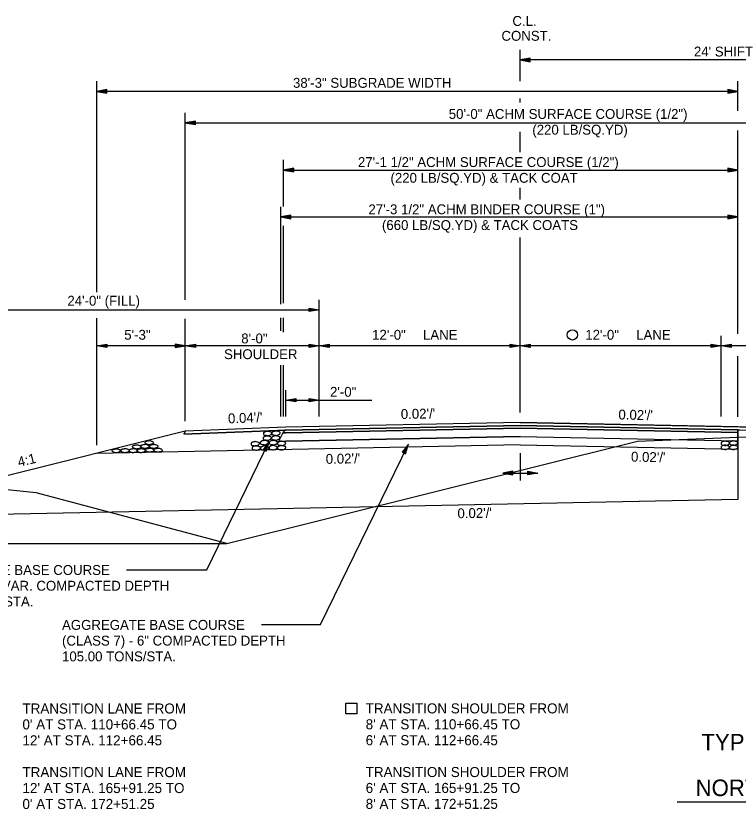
# Model space of a CAD drawing. Extents: x 1398565 to 1398920, y 1968324 to 1968581.
# Drawn here: x 1398599.68 to 1398642.81, y 1968480.86 to 1968528.22 of the extents above; entities that cross this region are included whole.
import ezdxf

# ---------------------------------------------------------------- set-up
doc = ezdxf.new("R2010")
doc.units = 0
for name, color, linetype in [('1', 7, 'Continuous'), ('10', 7, 'Continuous'), ('19', 7, 'Continuous'), ('42', 7, 'Continuous'), ('7', 7, 'Continuous'), ('Level 1', 7, 'Continuous')]:
    doc.layers.add(name, color=color, linetype=linetype)

# ---------------------------------------------------------------- blocks, each defined once
blk = doc.blocks.new('ROCKS')
at = {"layer": '1'}
blk.add_spline([(0.013, 0.06), (0.053, 0.053), (0.107, 0.033), (0.133, 0.013), (0.133, -0.007), (0.12, -0.033), (0.107, -0.04), (0.073, -0.053), (0.033, -0.067), (0.013, -0.067), (-0.02, -0.06), (-0.06, -0.053), (-0.087, -0.047), (-0.113, -0.02), (-0.113, -0.007), (-0.107, 0.02), (-0.087, 0.033), (-0.067, 0.047), (-0.033, 0.053), (-0.02, 0.06), (0.013, 0.06)], degree=3, dxfattribs=at)
blk = doc.blocks.new('4TO1 ABC')
at = {"layer": '1', "xscale": 0.1312491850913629, "yscale": 0.1312491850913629, "rotation": 180}
for p in [(0.00175, -0.00875), (-0.03325, -0.0385), (-0.016625, -0.023625), (0, -0.0385), (0.018375, -0.023625), (0.034125, -0.04025), (0.051625, -0.025375), (0.06475, -0.04025), (0.098, -0.04025), (0.133, -0.041125)]:
    blk.add_blockref('ROCKS', p, dxfattribs=at)

msp = doc.modelspace()

# ---------------------------------------------------------------- linework, layer by layer
at = {"layer": '10'}
msp.add_lwpolyline([(1398619.391, 1968487.191), (1398620.032, 1968487.191), (1398620.032, 1968486.549), (1398619.391, 1968486.549)], close=True, dxfattribs=at)
msp.add_circle((1398632.909, 1968509.169), 0.306, dxfattribs=at)
at = {"layer": '19'}
for p, q in [((1398630.395, 1968525.69), (1398629.795, 1968525.585)), ((1398653.795, 1968525.585), (1398629.795, 1968525.585)), ((1398629.795, 1968525.585), (1398630.395, 1968525.48)), ((1398630.395, 1968525.635), (1398629.955, 1968525.6)), ((1398629.955, 1968525.57), (1398630.395, 1968525.53)), ((1398630.395, 1968525.48), (1398630.395, 1968525.69)), ((1398604.509, 1968511.718), (1398604.509, 1968524.31)), ((1398642.795, 1968522.541), (1398642.795, 1968524.31)), ((1398605.109, 1968523.815), (1398604.509, 1968523.71)), ((1398642.795, 1968523.71), (1398604.509, 1968523.71)), ((1398604.509, 1968523.71), (1398605.109, 1968523.605)), ((1398605.109, 1968523.76), (1398604.669, 1968523.725)), ((1398604.669, 1968523.695), (1398605.109, 1968523.655)), ((1398605.109, 1968523.605), (1398605.109, 1968523.815)), ((1398642.195, 1968523.815), (1398642.195, 1968523.605)), ((1398642.795, 1968523.71), (1398642.195, 1968523.815)), ((1398642.635, 1968523.725), (1398642.195, 1968523.76)), ((1398642.195, 1968523.605), (1398642.795, 1968523.71)), ((1398642.195, 1968523.655), (1398642.635, 1968523.695)), ((1398609.795, 1968511.264), (1398609.795, 1968522.435)), ((1398610.395, 1968521.94), (1398609.795, 1968521.835)), ((1398609.795, 1968521.835), (1398659.795, 1968521.835)), ((1398609.795, 1968521.835), (1398610.395, 1968521.73)), ((1398610.395, 1968521.885), (1398609.955, 1968521.85)), ((1398609.955, 1968521.82), (1398610.395, 1968521.78)), ((1398610.395, 1968521.73), (1398610.395, 1968521.94)), ((1398642.795, 1968509.227), (1398642.795, 1968521.383)), ((1398615.667, 1968516.846), (1398615.667, 1968519.613)), ((1398616.267, 1968519.118), (1398615.667, 1968519.013)), ((1398615.667, 1968519.013), (1398616.267, 1968518.908)), ((1398615.667, 1968519.013), (1398642.795, 1968519.013)), ((1398616.267, 1968519.063), (1398615.827, 1968519.028)), ((1398615.827, 1968518.998), (1398616.267, 1968518.958)), ((1398616.267, 1968518.908), (1398616.267, 1968519.118)), ((1398642.195, 1968519.118), (1398642.195, 1968518.908)), ((1398642.795, 1968519.013), (1398642.195, 1968519.118)), ((1398642.635, 1968519.028), (1398642.195, 1968519.063)), ((1398642.195, 1968518.908), (1398642.795, 1968519.013)), ((1398642.195, 1968518.958), (1398642.635, 1968518.998)), ((1398615.497, 1968511.016), (1398615.497, 1968516.815)), ((1398616.097, 1968516.32), (1398615.497, 1968516.215)), ((1398615.497, 1968516.215), (1398642.795, 1968516.215)), ((1398615.497, 1968516.215), (1398616.097, 1968516.11)), ((1398616.097, 1968516.265), (1398615.657, 1968516.23)), ((1398615.657, 1968516.2), (1398616.097, 1968516.16)), ((1398616.097, 1968516.11), (1398616.097, 1968516.32)), ((1398642.195, 1968516.32), (1398642.195, 1968516.11)), ((1398642.795, 1968516.215), (1398642.195, 1968516.32)), ((1398642.635, 1968516.23), (1398642.195, 1968516.265)), ((1398642.195, 1968516.11), (1398642.795, 1968516.215)), ((1398642.195, 1968516.16), (1398642.635, 1968516.2)), ((1398615.667, 1968511.057), (1398615.667, 1968515.688)), ((1398617.795, 1968504.296), (1398617.795, 1968511.264)), ((1398593.795, 1968510.664), (1398617.795, 1968510.664)), ((1398617.195, 1968510.559), (1398617.195, 1968510.769)), ((1398617.195, 1968510.769), (1398617.795, 1968510.664)), ((1398617.195, 1968510.714), (1398617.635, 1968510.679)), ((1398617.795, 1968510.664), (1398617.195, 1968510.559)), ((1398617.635, 1968510.649), (1398617.195, 1968510.609)), ((1398604.509, 1968502.584), (1398604.509, 1968510.168)), ((1398609.795, 1968504.017), (1398609.795, 1968510.127)), ((1398615.497, 1968509.424), (1398615.497, 1968510.189)), ((1398615.667, 1968509.341), (1398615.667, 1968510.189)), ((1398641.795, 1968504.296), (1398641.795, 1968509.12)), ((1398604.509, 1968508.52), (1398605.109, 1968508.625)), ((1398631.795, 1968508.52), (1398604.509, 1968508.52)), ((1398605.109, 1968508.415), (1398604.509, 1968508.52)), ((1398604.669, 1968508.535), (1398605.109, 1968508.57)), ((1398605.109, 1968508.465), (1398604.669, 1968508.505)), ((1398605.109, 1968508.625), (1398605.109, 1968508.415)), ((1398609.195, 1968508.625), (1398609.195, 1968508.415)), ((1398609.795, 1968508.52), (1398609.195, 1968508.625)), ((1398609.635, 1968508.535), (1398609.195, 1968508.57)), ((1398609.195, 1968508.415), (1398609.795, 1968508.52)), ((1398609.195, 1968508.465), (1398609.635, 1968508.505)), ((1398609.795, 1968508.52), (1398610.395, 1968508.625)), ((1398610.395, 1968508.415), (1398609.795, 1968508.52)), ((1398609.955, 1968508.535), (1398610.395, 1968508.57)), ((1398610.395, 1968508.465), (1398609.955, 1968508.505)), ((1398610.395, 1968508.625), (1398610.395, 1968508.415)), ((1398617.195, 1968508.415), (1398617.195, 1968508.625)), ((1398617.195, 1968508.625), (1398617.795, 1968508.52)), ((1398617.195, 1968508.57), (1398617.635, 1968508.535)), ((1398617.795, 1968508.52), (1398617.195, 1968508.415)), ((1398617.635, 1968508.505), (1398617.195, 1968508.465)), ((1398617.795, 1968508.52), (1398618.395, 1968508.625)), ((1398618.395, 1968508.415), (1398617.795, 1968508.52)), ((1398617.955, 1968508.535), (1398618.395, 1968508.57)), ((1398618.395, 1968508.465), (1398617.955, 1968508.505)), ((1398618.395, 1968508.625), (1398618.395, 1968508.415)), ((1398629.195, 1968508.415), (1398629.195, 1968508.625)), ((1398629.195, 1968508.625), (1398629.795, 1968508.52)), ((1398629.195, 1968508.57), (1398629.635, 1968508.535)), ((1398629.795, 1968508.52), (1398629.195, 1968508.415)), ((1398629.635, 1968508.505), (1398629.195, 1968508.465)), ((1398629.795, 1968508.52), (1398630.395, 1968508.625)), ((1398630.395, 1968508.415), (1398629.795, 1968508.52)), ((1398629.955, 1968508.535), (1398630.395, 1968508.57)), ((1398630.395, 1968508.465), (1398629.955, 1968508.505)), ((1398630.395, 1968508.625), (1398630.395, 1968508.415)), ((1398643.795, 1968508.52), (1398631.795, 1968508.52)), ((1398641.195, 1968508.415), (1398641.195, 1968508.625)), ((1398641.195, 1968508.625), (1398641.795, 1968508.52)), ((1398641.195, 1968508.57), (1398641.635, 1968508.535)), ((1398641.795, 1968508.52), (1398641.195, 1968508.415)), ((1398641.635, 1968508.505), (1398641.195, 1968508.465)), ((1398641.795, 1968508.52), (1398642.395, 1968508.625)), ((1398642.395, 1968508.415), (1398641.795, 1968508.52)), ((1398641.955, 1968508.535), (1398642.395, 1968508.57)), ((1398642.395, 1968508.465), (1398641.955, 1968508.505)), ((1398642.395, 1968508.625), (1398642.395, 1968508.415)), ((1398642.795, 1968504.276), (1398642.795, 1968507.904)), ((1398615.497, 1968504.296), (1398615.497, 1968507.356)), ((1398615.667, 1968504.296), (1398615.667, 1968507.356)), ((1398615.795, 1968504.296), (1398615.795, 1968505.874)), ((1398615.795, 1968505.274), (1398616.395, 1968505.379)), ((1398615.795, 1968505.274), (1398620.942, 1968505.274)), ((1398616.395, 1968505.169), (1398615.795, 1968505.274)), ((1398615.955, 1968505.289), (1398616.395, 1968505.324)), ((1398616.395, 1968505.219), (1398615.955, 1968505.259)), ((1398616.395, 1968505.379), (1398616.395, 1968505.169)), ((1398617.195, 1968505.169), (1398617.195, 1968505.379)), ((1398617.195, 1968505.379), (1398617.795, 1968505.274)), ((1398617.195, 1968505.324), (1398617.635, 1968505.289)), ((1398617.795, 1968505.274), (1398617.195, 1968505.169)), ((1398617.635, 1968505.259), (1398617.195, 1968505.219)), ((1398629.795, 1968503.936), (1398615.795, 1968503.656)), ((1398629.795, 1968503.77), (1398615.795, 1968503.49)), ((1398629.795, 1968503.936), (1398655.795, 1968503.416)), ((1398629.795, 1968503.77), (1398655.795, 1968503.25)), ((1398609.795, 1968503.416), (1398593.795, 1968499.416)), ((1398615.795, 1968503.49), (1398609.71, 1968503.246)), ((1398609.795, 1968503.416), (1398609.71, 1968503.246)), ((1398615.795, 1968503.656), (1398609.795, 1968503.416)), ((1398615.625, 1968503.316), (1398615.37, 1968502.806)), ((1398615.71, 1968503.486), (1398615.625, 1968503.316)), ((1398615.795, 1968503.323), (1398615.625, 1968503.316)), ((1398629.795, 1968503.603), (1398615.795, 1968503.323)), ((1398629.795, 1968503.603), (1398642.795, 1968503.343)), ((1398642.795, 1968503.343), (1398629.795, 1968503.603)), ((1398642.795, 1968503.51), (1398642.795, 1968502.051)), ((1398642.795, 1968502.843), (1398642.795, 1968503.343)), ((1398642.795, 1968503.343), (1398642.795, 1968503.343)), ((1398611.074, 1968495.146), (1398614.802, 1968502.804)), ((1398614.802, 1968502.804), (1398614.438, 1968502.315)), ((1398614.625, 1968502.223), (1398614.802, 1968502.804)), ((1398615.795, 1968502.823), (1398615.37, 1968502.806)), ((1398629.795, 1968503.103), (1398615.795, 1968502.823)), ((1398629.795, 1968503.103), (1398642.795, 1968502.843)), ((1398629.795, 1968503.103), (1398642.795, 1968502.843)), ((1398629.795, 1968502.601), (1398604.509, 1968502.095)), ((1398614.72, 1968502.668), (1398614.487, 1968502.294)), ((1398614.581, 1968502.246), (1398614.745, 1968502.655)), ((1398617.873, 1968491.886), (1398623.114, 1968502.652)), ((1398623.114, 1968502.652), (1398622.75, 1968502.163)), ((1398623.031, 1968502.515), (1398622.799, 1968502.142)), ((1398622.893, 1968502.093), (1398623.056, 1968502.502)), ((1398622.937, 1968502.07), (1398623.114, 1968502.652)), ((1398629.795, 1968502.601), (1398642.795, 1968502.341)), ((1398614.438, 1968502.315), (1398614.625, 1968502.223)), ((1398622.75, 1968502.163), (1398622.937, 1968502.07)), ((1398642.795, 1968502.051), (1398642.795, 1968499.341)), ((1398642.795, 1968499.341), (1398590.426, 1968498.293)), ((1398606.276, 1968495.146), (1398611.074, 1968495.146)), ((1398614.345, 1968491.886), (1398617.873, 1968491.886)), ((1398639.176, 1968481.304), (1398668.156, 1968481.304))]:
    msp.add_line(p, q, dxfattribs=at)
for points in [[(1398609.712, 1968503.251), (1398615.795, 1968503.49), (1398629.795, 1968503.77), (1398655.795, 1968503.25), (1398659.88, 1968503.086), (1398659.795, 1968503.256), (1398655.795, 1968503.416), (1398629.795, 1968503.936), (1398615.795, 1968503.656), (1398609.795, 1968503.416)], [(1398615.625, 1968503.316), (1398615.795, 1968503.323), (1398629.795, 1968503.603), (1398642.795, 1968503.343), (1398642.795, 1968503.51), (1398629.795, 1968503.77), (1398615.795, 1968503.49), (1398615.71, 1968503.486)]]:
    msp.add_lwpolyline(points, close=True, dxfattribs=at)
for points in [[(1398629.795, 1968503.603), (1398615.795, 1968503.323), (1398615.625, 1968503.316), (1398615.37, 1968502.806)], [(1398615.37, 1968502.806), (1398615.795, 1968502.823), (1398629.795, 1968503.103)]]:
    msp.add_lwpolyline(points, dxfattribs=at)
at = {"layer": '42'}
for p, q in [((1398629.795, 1968502.103), (1398629.795, 1968500.47)), ((1398629.347, 1968501.027), (1398628.747, 1968500.922)), ((1398628.747, 1968500.922), (1398629.347, 1968500.817)), ((1398628.747, 1968500.922), (1398630.842, 1968500.922)), ((1398629.347, 1968500.972), (1398628.907, 1968500.937)), ((1398628.907, 1968500.907), (1398629.347, 1968500.867)), ((1398629.347, 1968500.817), (1398629.347, 1968501.027)), ((1398630.242, 1968500.817), (1398630.242, 1968501.027)), ((1398630.242, 1968501.027), (1398630.842, 1968500.922)), ((1398630.242, 1968500.972), (1398630.682, 1968500.937)), ((1398630.842, 1968500.922), (1398630.242, 1968500.817)), ((1398630.682, 1968500.907), (1398630.242, 1968500.867))]:
    msp.add_line(p, q, dxfattribs=at)
for points in [[(1398612.268, 1968496.72), (1398600.898, 1968499.734), (1398598.177, 1968500.018), (1398595.382, 1968501.049), (1398585.177, 1968502.861), (1398565.203, 1968503.547)], [(1398642.795, 1968503.07), (1398653.795, 1968503.29)], [(1398565.772, 1968496.72), (1398612.268, 1968496.72), (1398636.795, 1968502.83), (1398642.795, 1968503.07)], [(1398565.772, 1968496.72), (1398612.268, 1968496.72), (1398636.795, 1968502.83), (1398642.795, 1968503.07)]]:
    msp.add_lwpolyline(points, dxfattribs=at)
at = {"layer": '7'}
for p, q in [((1398629.795, 1968524.319), (1398629.795, 1968526.185)), ((1398629.795, 1968523.037), (1398629.795, 1968523.285)), ((1398629.795, 1968520.071), (1398629.795, 1968521.301)), ((1398629.795, 1968517.259), (1398629.795, 1968517.941)), ((1398629.795, 1968504.536), (1398629.795, 1968514.985))]:
    msp.add_line(p, q, dxfattribs=at)

# ---------------------------------------------------------------- block references
at = {"layer": '19', "xscale": 14.999970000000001, "yscale": -14.999970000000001, "rotation": 180}
msp.add_blockref('4TO1 ABC', (1398607.649, 1968502.863), dxfattribs=at)
at = {"layer": 'Level 1', "xscale": 2.011654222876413, "yscale": 2.011654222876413, "rotation": 1.8263814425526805}
for p in [(1398614.69, 1968503.293), (1398615.189, 1968503.308), (1398613.952, 1968502.678), (1398614.496, 1968502.748), (1398614.663, 1968503.013), (1398615.029, 1968502.744), (1398615.175, 1968503.025), (1398615.52, 1968502.7), (1398642.015, 1968502.705), (1398642.514, 1968502.72), (1398614.012, 1968502.423), (1398614.516, 1968502.422), (1398615.021, 1968502.443), (1398615.526, 1968502.442), (1398642.015, 1968502.463), (1398642.52, 1968502.462)]:
    msp.add_blockref('ROCKS', p, dxfattribs=at)

# ---------------------------------------------------------------- texts
at = {"layer": '10'}
for s, height, rotation, p in [('24\'-0" (FILL)', 0.59001, 360, (1398602.754, 1968510.916)), ('5\'-3"', 0.59, 360, (1398606.151, 1968508.883)), ('12\'-0" ', 0.59, 360, (1398620.952, 1968508.883)), ('LANE', 0.59, 360, (1398623.991, 1968508.883)), ('12\'-0" ', 0.59, 360, (1398633.681, 1968508.883)), ('LANE', 0.59, 360, (1398636.72, 1968508.883)), ('8\'-0" ', 0.59, 360, (1398613.136, 1968508.665)), ('SHOULDER', 0.59, 360, (1398612.11, 1968507.725)), ('2\'-0"', 0.59, 360, (1398618.437, 1968505.477)), ('4:1', 0.59, 13.7364, (1398599.863, 1968501.284))]:
    msp.add_text(s, height=height, rotation=rotation, dxfattribs=at).set_placement(p)
at = {"layer": '19'}
msp.add_text('C.L.', height=0.59, dxfattribs=at).set_placement((1398629.329, 1968527.618))
for s, height, rotation, p in [('CONST.', 0.59, 360, (1398628.675, 1968526.73)), ("24' SHIFT", 0.59, 360, (1398640.167, 1968525.792)), ("0.02'/'", 0.59, 1.1458, (1398622.67, 1968504.15)), ("0.02'/'", 0.59, 358.8542, (1398635.654, 1968504.123)), ("0.04'/'", 0.59, 2.2906, (1398612.356, 1968503.887)), ("0.02'/'", 0.59, 1.1458, (1398618.188, 1968501.47)), ("0.02'/'", 0.59, 358.8542, (1398636.406, 1968501.608)), ("0.02'/'", 0.59, 1.1458, (1398626.053, 1968498.222)), ('AGGREGATE BASE COURSE', 0.59001, 360, (1398594.371, 1968494.842)), ('(CLASS 7) - VAR. COMPACTED DEPTH', 0.59001, 360, (1398594.371, 1968493.902)), ('76.25 TONS/STA.', 0.59001, 360, (1398594.371, 1968492.962)), ('AGGREGATE BASE COURSE', 0.59001, 360, (1398602.435, 1968491.565)), ('(CLASS 7) - 6" COMPACTED DEPTH', 0.59001, 360, (1398602.435, 1968490.625)), ('105.00 TONS/STA.', 0.59001, 360, (1398602.435, 1968489.685)), ('TYPICAL SECTION OF IMPROVEMENT', 0.98999, 360, (1398640.613, 1968484.362)), ('NORTHBOUND PASSING LANE (SITE 1)', 0.98999, 360, (1398640.266, 1968481.639))]:
    msp.add_text(s, height=height, rotation=rotation, dxfattribs=at).set_placement(p)
at = {"layer": '42'}
for s, p in [('38\'-3" SUBGRADE WIDTH', (1398616.227, 1968523.923)), ('50\'-0" ACHM SURFACE COURSE (1/2")', (1398625.527, 1968522.066)), ('(220 LB/SQ.YD)', (1398630.517, 1968521.126)), ('27\'-1 1/2" ACHM SURFACE COURSE (1/2")', (1398620.104, 1968519.192)), ('(220 LB/SQ.YD) & TACK COAT', (1398622.048, 1968518.252)), ('27\'-3 1/2" ACHM BINDER COURSE (1")', (1398620.73, 1968516.373)), ('(660 LB/SQ.YD) & TACK COATS', (1398621.538, 1968515.433))]:
    msp.add_text(s, height=0.59001, rotation=360, dxfattribs=at).set_placement(p)
for s, p in [('TRANSITION LANE FROM', (1398600.072, 1968486.57)), ('TRANSITION SHOULDER FROM', (1398620.567, 1968486.576)), ("0' AT STA. 110+66.45 TO", (1398600.072, 1968485.62)), ("8' AT STA. 110+66.45 TO", (1398620.567, 1968485.626)), ("12' AT STA. 112+66.45", (1398600.072, 1968484.67)), ("6' AT STA. 112+66.45", (1398620.567, 1968484.676)), ('TRANSITION LANE FROM', (1398600.072, 1968482.77)), ('TRANSITION SHOULDER FROM', (1398620.567, 1968482.776)), ("6' AT STA. 165+91.25 TO", (1398620.567, 1968481.826)), ("12' AT STA. 165+91.25 TO", (1398600.072, 1968481.82)), ("8' AT STA. 172+51.25", (1398620.567, 1968480.876)), ("0' AT STA. 172+51.25", (1398600.072, 1968480.87))]:
    msp.add_text(s, height=0.6, dxfattribs=at).set_placement(p)

doc.saveas('drawing.dxf')
